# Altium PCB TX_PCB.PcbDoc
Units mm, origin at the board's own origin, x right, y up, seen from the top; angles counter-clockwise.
Board outline 84.96 x 70.99 mm, 2 copper layers (Top Layer, Bottom Layer); 90 components, 66 nets, 345 pads, 0 vias.
Unrouted connection lines stored in the file: 215.
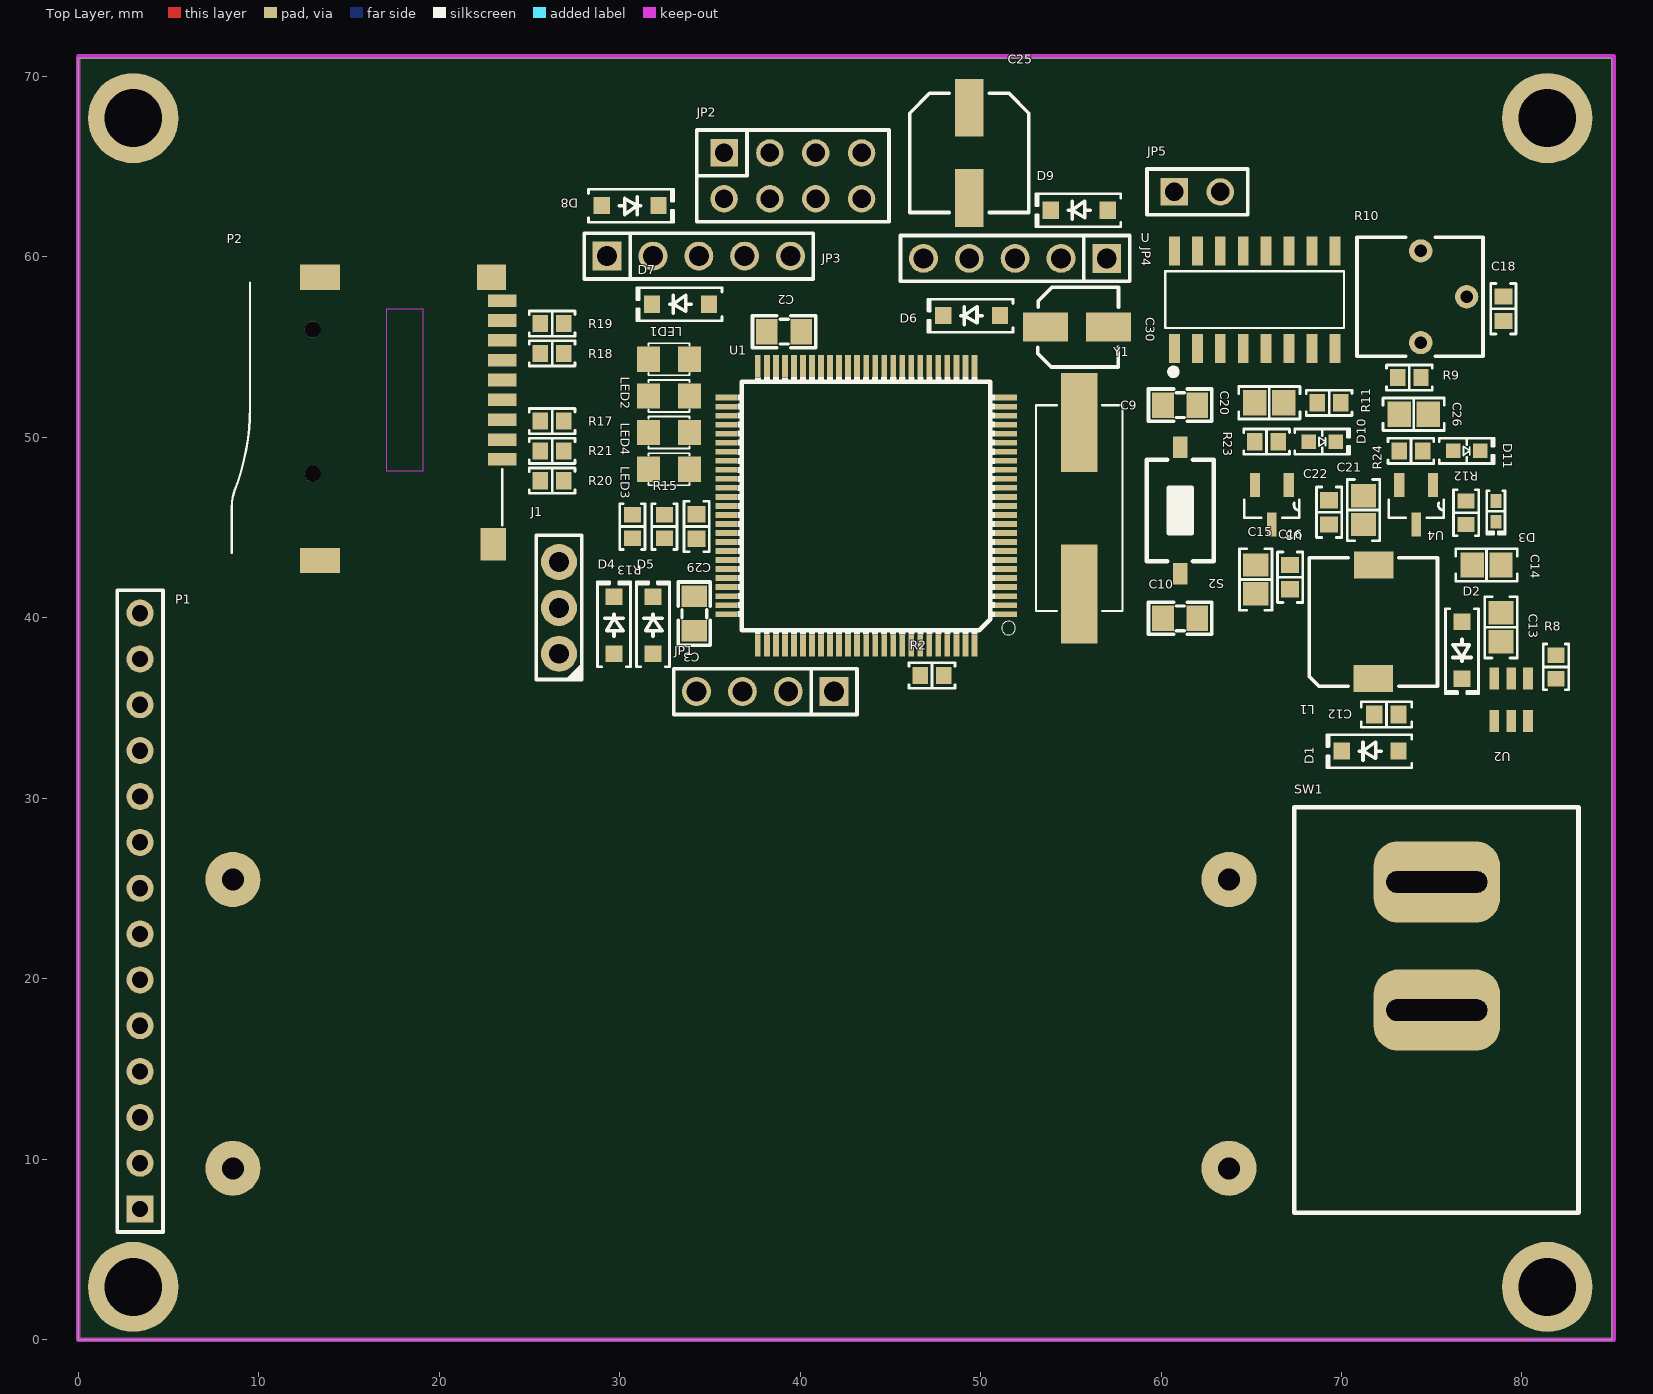
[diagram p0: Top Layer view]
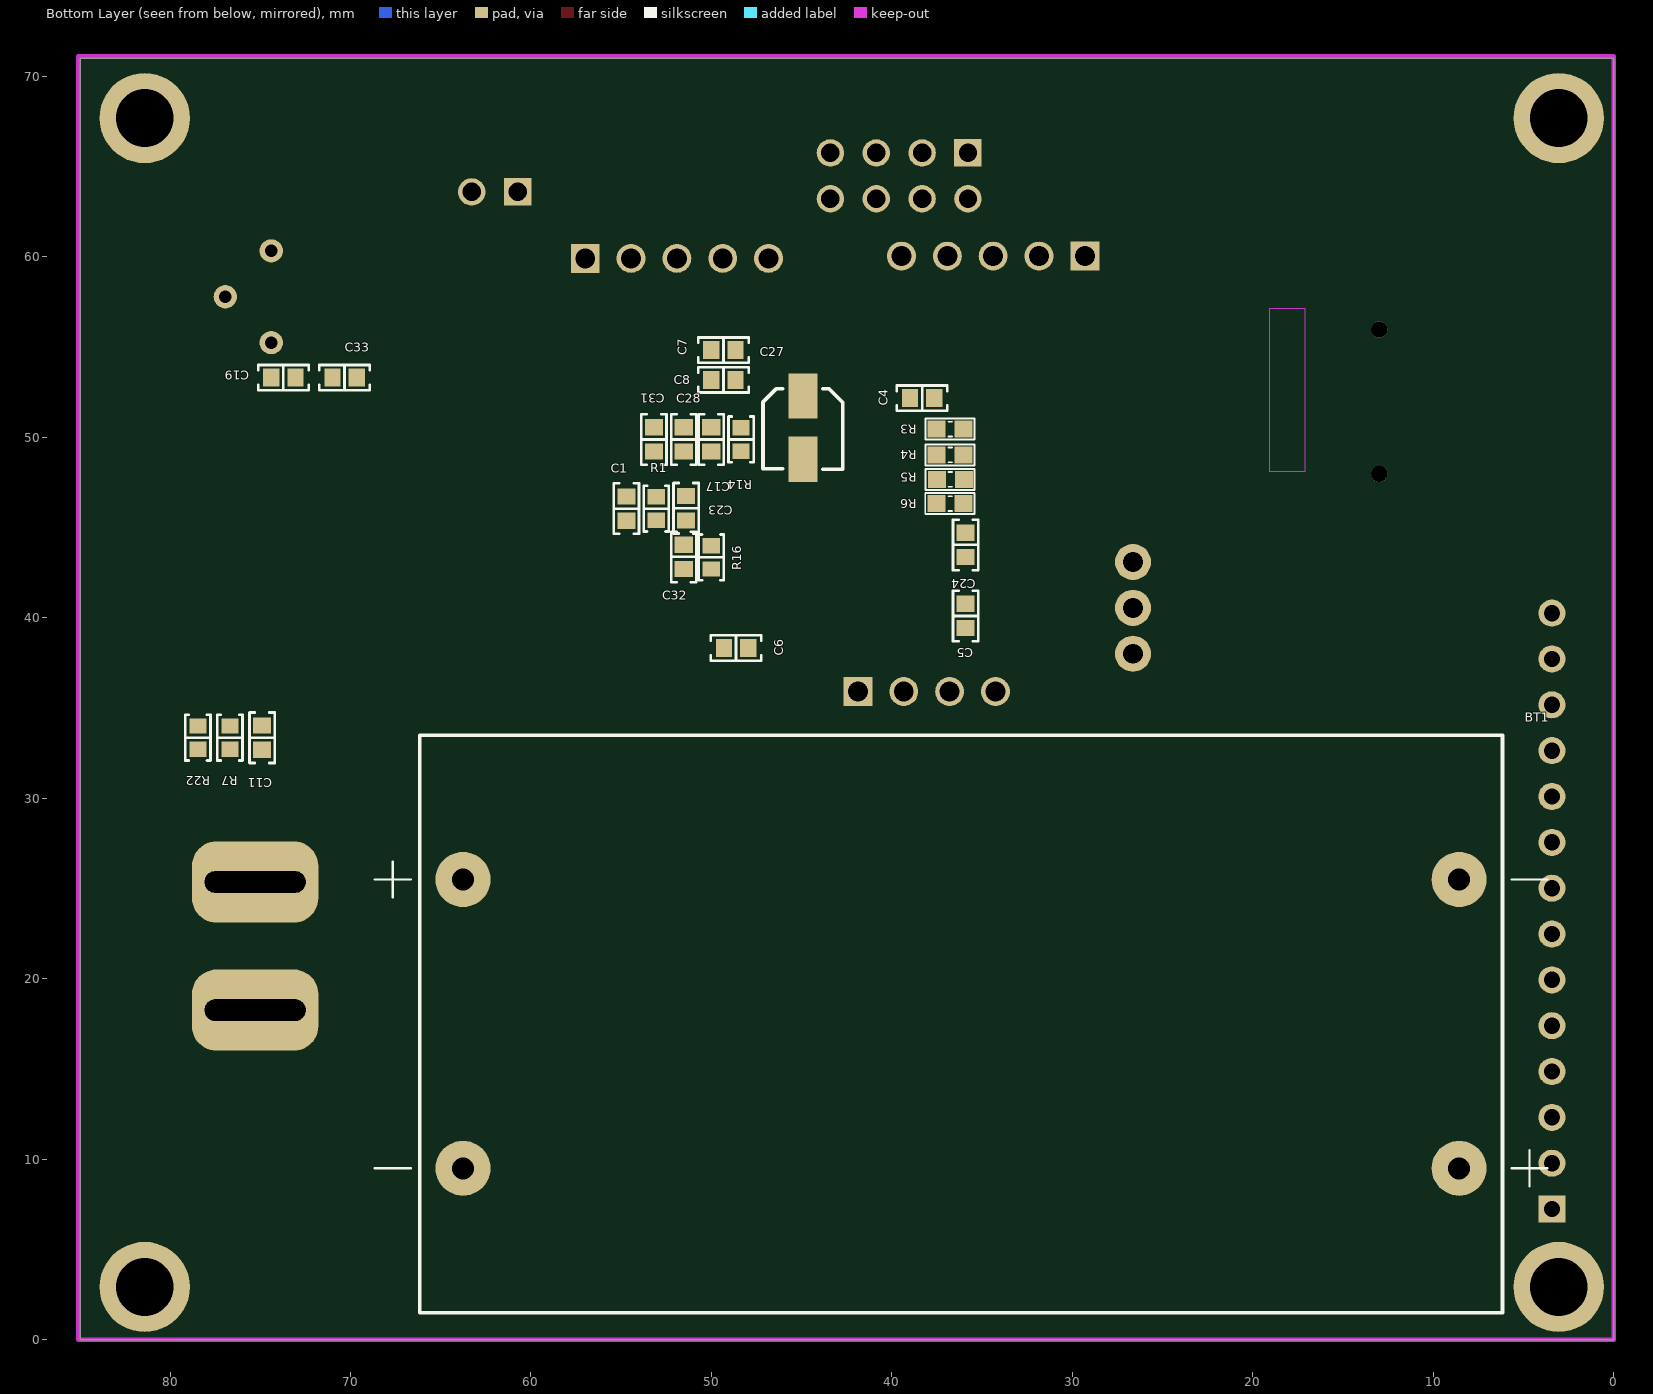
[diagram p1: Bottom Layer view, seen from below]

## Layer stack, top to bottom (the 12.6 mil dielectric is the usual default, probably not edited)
Top Solder: solder mask 0.0102, Solder Resist, Dk 3.5
Top Layer: signal copper 0.0356
Dielectric 1: dielectric 0.32, FR-4, Dk 4.8
Bottom Layer: signal copper 0.0356
Bottom Solder: solder mask 0.0102, Solder Resist, Dk 3.5

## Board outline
0,0 0,70.993 84.963,70.993 84.963,0

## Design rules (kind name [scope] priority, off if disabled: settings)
Clearance [All] p1: gap=0.127 ignorepadtopadclearanceinfootprint=FALSE
PolygonConnect [All] p1: connectstyle=Relief reliefconductorwidth=0.254 reliefentries=4 polygonreliefangle="90 Angle" airgapwidth=0.254
RoutingVias [All] p1: holewidth=0.711 width=1.27 viastyle="Through Hole" minholewidth=0.711 minwidth=1.27 maxholewidth=0.711 maxwidth=1.27
SolderMaskExpansion [All] p1: expansion=0.102 istentingtop=FALSE
Width [All] p1: maxlimit=0.254 minlimit=0.254 preferedwidth=0.254
30 further rules are at their usual default settings.

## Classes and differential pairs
component class Audio: C18 C19 C33 JP5 P2 R9 R10 R11 R17 R18 R19 R20 R21 U
component class Power_2: BT1 C11 C12 C13 C14 C15 C16 C20 C21 C22 C26 D1 D2 D3 D10 D11 L1 R7 R8 R12 R22 R23 R24 SW1 U2 U3 U4
component class MAIN_TX: C1 C2 C3 C4 C5 C6 C7 C8 C9 C10 C17 C23 C24 C25 C27 C28 C29 C30 C31 C32 D4 D5 D6 D7 D8 D9 J1 JP1 JP2 JP3 JP4 LED1 LED2 LED3 LED4 P1 R1 R2 R3 R4 R5 R6 R13 R14 R15 R16 S2 U1 Y1

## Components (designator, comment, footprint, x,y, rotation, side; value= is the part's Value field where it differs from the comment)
BT1 "18650" "DE PIN 18650 X2" 36.168,17.499 r180 bottom
C1 "0.1 µF" "CAP 0603_1608" 54.71,46.051 r90 bottom
C2 "2.2uF" "tu 0805" 39.115,55.853 r180 top
C3 "2.2uF" "tu 0805" 34.136,40.232 r90 top
C4 "0.1 µF" "CAP 0603_1608" 38.327,52.17 r180 bottom
C5 "=Value" "CAP 0603_1608" 35.914,40.105 r270 bottom
C6 "0.1 µF" "CAP 0603_1608" 48.636,38.327 r0 bottom
C7 "=Value" "CAP 0603_1608" 49.336,54.837 r180 bottom
C8 "=Value" "CAP 0603_1608" 49.336,53.186 r180 bottom
C9 "20pF" "tu 0805" 61.06,51.789 r0 top
C10 "20pF" "tu 0805" 61.06,39.978 r0 top
C11 "10000 pF" "CAP 0603_1608" 74.903,33.359 r270 bottom
C12 "10000 pF" "CAP 0603_1608" 72.49,34.644 r0 top
C13 "10 µF" "CAP 0805_2012" 78.84,39.47 r270 top
C14 "22 µF" "CAP 0805_2012" 78.04,42.927 r180 top
C15 "10 µF" "CAP 0805_2012" 65.251,42.127 r90 top
C16 "0.1µF" "CAP 0603_1608" 67.156,42.252 r90 top
C17 "0.1 µF" "CAP 0603_1608" 50.011,49.884 r270 bottom
C18 "0.22 µF" "CAP 0603_1608" 78.967,57.123 r90 top
C19 "0.1 µF" "CAP 0603_1608" 73.72,53.313 r0 bottom
C20 "10 µF" "CAP 0805_2012" 66,51.916 r180 top
C21 "10 µF" "CAP 0805_2012" 71.22,45.97 r270 top
C22 "0.1µF" "CAP 0603_1608" 69.315,45.845 r270 top
C23 "0.1 µF" "CAP 0603_1608" 51.408,46.074 r270 bottom
C24 "0.1 µF" "CAP 0603_1608" 35.914,44.042 r270 bottom
C25 "220 µF" "CAP ALSMD 6.6MM H6.1MM" 49.376,65.759 r270 top
C26 "10 µF" "CAP 0805_2012" 74.001,51.281 r180 top
C27 "1 µF" "CAP ALSMD 4.3MM H5.4MM" 44.931,50.534 r270 bottom
C28 "0.1 µF" "CAP 0603_1608" 51.535,49.884 r270 bottom
C29 "0.1 µF" "CAP 0603_1608" 34.263,45.058 r270 top
C30 "1 µF" "CAP ALSMD 4.3MM H5.4MM" 55.345,56.107 r0 top
C31 "0.1 µF" "CAP 0603_1608" 53.186,49.884 r90 bottom
C32 "1 µF" "CAP 0603_1608" 51.535,43.376 r270 bottom
C33 "1 µF" "CAP 0603_1608" 70.331,53.313 r180 bottom
D1 "1N5819HW-7-F" SOD-123 71.59,32.612 r180 top
D2 "1N5819HW-7-F" SOD-123 76.681,38.202 r270 top
D3 "Green" "LED 0402_1005 GREEN" 78.558,45.897 r270 top
D4 "1N5819HW-7-F" SOD-123 29.691,39.586 r90 top
D5 "1N5819HW-7-F" SOD-123 31.85,39.586 r90 top
D6 "1N5819HW-7-F" SOD-123 49.503,56.742 r180 top
D7 "1N5819HW-7-F" SOD-123 33.374,57.377 r180 top
D8 "1N5819HW-7-F" SOD-123 30.58,62.838 r0 top
D9 "1N5819HW-7-F" SOD-123 55.472,62.584 r180 top
D10 "Yellow" "LED 0603_1608 YELLOW" 68.934,49.757 r0 top
D11 "Yellow" "LED 0603_1608 YELLOW" 76.935,49.249 r0 top
J1 "M20-7820342" "HARWIN M20-7820345" 26.643,40.551 r180 top
JP1 "JP 1x4 2.54" "JP 1x4 DT" 41.883,35.914 r180 top
JP2 "JP 2x4 2.54" "JP 2x4 CT" 39.597,64.489 r0 top
JP3 "JP 1x5 2.54" "JP 1x5 DT" 29.31,60.044 r0 top
JP4 "JP 1x5 2.54" "JP 1x5 DT" 56.996,59.917 r180 top
JP5 "JP 1x2 2.54" "JP 1x2 CT" 60.744,63.6 r0 top
L1 "10µH" "TDK SLF7032" 71.773,39.777 r90 top
LED1 "LED 0805" LED-0805-Red 33.882,54.329 r180 top
LED2 "LED 0805" LED-0805-Yellow 33.882,52.297 r180 top
LED3 "LED 0805" LED-0805-Green 33.882,48.233 r180 top
LED4 "LED 0805" LED-0805-Orange 33.882,50.265 r180 top
P1 "Header 14" HDR1X14 3.429,7.239 r90 top
P2 "ST-TF-003A" SUNTECH_ST-TF-003A 18.165,52.297 r270 top
R1 "100 kOhms" "RES 0603_1608" 53.059,46.051 r270 bottom
R2 "10 kOhms" "RES 0603_1608" 47.311,36.803 r0 top
R3 "680R" "tro smd 0603" 36.774,50.457 r0 bottom
R4 "680R" "tro smd 0603" 36.773,49.022 r0 bottom
R5 "680R" "tro smd 0603" 36.762,47.668 r0 bottom
R6 "680R" "tro smd 0603" 36.778,46.328 r0 bottom
R7 "52.3 kOhms" "RES 0603_1608" 76.681,33.359 r270 bottom
R8 "100 kOhms" "RES 0603_1608" 81.888,37.277 r90 top
R9 "4.7 kOhms" "RES 0603_1608" 73.76,53.313 r0 top
R10 "10 kOhms" "BOURNS TRIMPOT 3362P-1" 74.649,57.791 r270 top
R11 "10 kOhms" "RES 0603_1608" 69.315,51.916 r180 top
R12 "1 kOhms" "RES 0603_1608" 76.904,45.82 r270 top
R13 "10 kOhms" "RES 0603_1608" 30.707,45.058 r270 top
R14 "47 Ohms" "RES 0603_1608" 48.36,49.884 r90 bottom
R15 "20 kOhms" "RES 0603_1608" 32.485,45.058 r270 top
R16 "0 Ohms" "RES 0603_1608" 50.011,43.351 r270 bottom
R17 "4.7 kOhms" "RES 0603_1608" 26.262,50.9 r0 top
R18 "4.7 kOhms" "RES 0603_1608" 26.262,54.648 r0 top
R19 "4.7 kOhms" "RES 0603_1608" 26.262,56.299 r0 top
R20 "4.7 kOhms" "RES 0603_1608" 26.262,47.598 r0 top
R21 "4.7 kOhms" "RES 0603_1608" 26.262,49.249 r0 top
R22 "10 kOhms" "RES 0603_1608" 78.459,33.359 r90 bottom
R23 "680 Ohms" "RES 0603_1608" 65.85,49.757 r180 top
R24 "680 Ohms" "RES 0603_1608" 73.851,49.249 r180 top
S2 "SW-SMD" SW-SMD 61.06,45.947 r90 top
SW1 "ROCKET SWITCH-10A" SW_2ARS_TH 75.259,25.31 r0 top
U "PAM8403DR" SOIC127P605X150-16N 65.189,57.631 r90 top
U1 "MCU-STM32F407VET6(LQFP100)" LQFP100-0.5-13.8X13.8MM 43.661,46.201 r180 top
U2 "LM2734YMK" SOT95P285X100-6N 79.399,35.458 r90 top
U3 "MCP1700T-3302E/TT" SOT95P237X112-3N 66.14,46.262 r270 top
U4 "MCP1700T-3302E/TT" SOT95P237X112-3N 74.141,46.262 r270 top
Y1 "ECS-80-S-5P-TR" XTAL_ECS-80-S-5P-TR 55.472,46.074 r270 top

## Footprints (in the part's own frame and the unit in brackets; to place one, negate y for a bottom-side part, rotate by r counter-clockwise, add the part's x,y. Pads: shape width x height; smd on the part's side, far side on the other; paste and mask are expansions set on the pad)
"BOURNS TRIMPOT 3362P-1" [mm] "3362 -1/4 ? Square Trimpot® Trimming Potentiometer"
  round 1.29 hole 0.69: 1(-2.54,-0.254) 2(0,2.286) 3(2.54,-0.254)
  silkscreen extent -3.3,-3.79 3.3,3.2, body extent -3.3,-3.79 3.3,3.2, height 4.7
"CAP 0603_1608" [mm] "Chip Capacitor, 2-Leads, Body 1.60x0.80mm, IPC Medium Density"
  rect 0.9x1 smd: 1(-0.675,0) 2(0.675,0)
  silkscreen extent -1.4,-0.7 1.4,0.7, body extent -0.8,-0.41 0.8,0.41, height 0.82
"CAP 0805_2012" [mm] "Chip Capacitor, 2-Leads, Body 2.00x1.20mm, IPC Medium Density"
  rect 1.3x1.4 smd: 1(-0.8,0) 2(0.8,0)
  silkscreen extent -1.7,-0.9 1.7,0.9, body extent -1,-0.64 1,0.64, height 1.26
"CAP ALSMD 4.3MM H5.4MM" [mm] "Aluminum Electrolytic Capacitor, Body 4.30x4.30x5.40mm, IPC Low Density"
  rect 2.5x1.6 smd: 1(-1.75,0) 2(1.75,0)
  silkscreen extent -2.17,-2.21 2.3,2.2, body extent -2.3,-2.2 2.3,2.2, height 5.4
"CAP ALSMD 6.6MM H6.1MM" [mm] "Aluminum Electrolytic Capacitor, Body 6.60x6.60x6.10mm, IPC Low Density"
  rect 3.2x1.6 smd: 1(-2.5,0) 2(2.5,0)
  silkscreen extent -3.3,-3.3 3.3,3.3, body extent -3.5,-3.3 3.5,3.3, height 6.1
"DE PIN 18650 X2" [mil] "2-cell AA battery holder"
  round 120 hole 48: 1(-1086.61,314.96) 1(1086.61,314.96) 2(-1086.61,-314.96) 2(1086.61,-314.96)
  silkscreen extent -1280,-630 1280,630, body extent -1181,-630 1181,630, height 657
"HARWIN M20-7820345" [mm] "2.54mm DIL PC TAIL PIN HEADER ASSEMBLY"
  round 2 hole 1.1: 1(0,2.54) 2(0,0) 3(0,-2.54)
  silkscreen extent -1.27,-4.03 1.27,4, body extent -1.25,-4.01 1.25,4.01, height 8.5
HDR1X14 [mm] "Connector; Header; 14 Position"
  rect 1.5x1.5 hole 0.9: 1(0,0)
  round 1.5 hole 0.9: 2(2.54,0) 3(5.08,0) 4(7.62,0) 5(10.16,0) 6(12.7,0) 7(15.24,0) 8(17.78,0) 9(20.32,0) 10(22.86,0) 11(25.4,0) 12(27.94,0) 13(30.48,0) 14(33.02,0)
  silkscreen extent -1.27,-1.27 34.29,1.27, body extent -1.27,-1.27 34.29,1.27, height 7
"JP 1x2 CT" [mm] "JP 1x2 CT"
  rect 1.52x1.52 hole 1.02: 1(0,0)
  round 1.52 hole 1.02: 2(2.54,0)
  silkscreen extent -1.52,-1.27 4.06,1.27, body extent -1.52,-1.25 4.06,1.25, height 8.51
"JP 1x4 DT" [mm] "4 pins, 1 row, straight, gold plating"
  rect 1.6x1.6 hole 1.1: 1(0,0)
  round 1.6 hole 1.1: 2(2.54,0) 3(5.08,0) 4(7.62,0)
  silkscreen extent -1.27,-1.27 8.89,1.27, body extent -1.27,-1.27 8.89,1.27, height 8.54
"JP 1x5 DT" [mm] "5 pins, 1 row, straight, gold plating"
  rect 1.6x1.6 hole 1.1: 1(0,0)
  round 1.6 hole 1.1: 2(2.54,0) 3(5.08,0) 4(7.62,0) 5(10.16,0)
  silkscreen extent -1.27,-1.27 11.43,1.27, body extent -1.27,-1.27 11.43,1.27, height 8.54
"JP 2x4 CT" [mm] "8 pins, dual row, straight, gold plating"
  rect 1.52x1.52 hole 1.02: 1(-3.81,1.27)
  round 1.52 hole 1.02: 2(-1.27,1.27) 3(1.27,1.27) 4(3.81,1.27) 5(3.81,-1.27) 6(1.27,-1.27) 7(-1.27,-1.27) 8(-3.81,-1.27)
  silkscreen extent -5.33,-2.54 5.33,2.54, body extent -5.33,-2.54 5.33,2.54, height 8.51
"LED 0402_1005 GREEN" [mm] "Chip Diode, 2-Leads, Body 1.00x0.50mm, IPC Medium Density"
  rect 0.75x0.6 smd: 1(-0.575,0) 2(0.575,0)
  silkscreen extent -1.14,-0.51 1.27,0.51, body extent -0.5,-0.25 0.5,0.25, height 0.21
"LED 0603_1608 YELLOW" [mm] "Chip Diode, 2-Leads, Body 1.60x0.80mm, IPC Medium Density"
  rect 0.8x0.8 smd: 1(-0.75,0) 2(0.75,0)
  silkscreen extent -1.52,-0.7 1.52,0.7, body extent -0.8,-0.4 0.8,0.4, height 0.53
LED-0805-Green [mil]
  rect 50x55 smd: 1(0,0) 2(90,0)
  silkscreen extent 0,-35 90,35, body extent 5,-25 85,25, height 43
LED-0805-Orange [mil]
  rect 50x55 smd: 1(0,0) 2(90,0)
  silkscreen extent 0,-35 90,35, body extent 5,-25 85,25, height 43
LED-0805-Red [mil]
  rect 50x55 smd: 1(0,0) 2(90,0)
  silkscreen extent 0,-35 90,35, body extent 5,-25 85,25, height 43
LED-0805-Yellow [mil]
  rect 50x55 smd: 1(0,0) 2(90,0)
  silkscreen extent 0,-35 90,35, body extent 5,-25 85,25, height 43
LQFP100-0.5-13.8X13.8MM [mm]
  rect 1.2x0.32 smd: 1(-7.75,6) 2(-7.75,5.5) 3(-7.75,5) 4(-7.75,4.5) 5(-7.75,4) 6(-7.75,3.5) 7(-7.75,3) 8(-7.75,2.5) 9(-7.75,2) 10(-7.75,1.5) 11(-7.75,1) 12(-7.75,0.5) 13(-7.75,0) 14(-7.75,-0.5) 15(-7.75,-1) 16(-7.75,-1.5) 17(-7.75,-2) 18(-7.75,-2.5) 19(-7.75,-3) 20(-7.75,-3.5) 21(-7.75,-4) 22(-7.75,-4.5) 23(-7.75,-5) 24(-7.75,-5.5) 25(-7.75,-6) 51(7.75,-6) 52(7.75,-5.5) 53(7.75,-5) 54(7.75,-4.5) 55(7.75,-4) 56(7.75,-3.5) 57(7.75,-3) 58(7.75,-2.5) 59(7.75,-2) 60(7.75,-1.5) 61(7.75,-1) 62(7.75,-0.5) 63(7.75,0) 64(7.75,0.5) 65(7.75,1) 66(7.75,1.5) 67(7.75,2) 68(7.75,2.5) 69(7.75,3) 70(7.75,3.5) 71(7.75,4) 72(7.75,4.5) 73(7.75,5) 74(7.75,5.5) 75(7.75,6)
  rect 0.32x1.2 smd: 26(-6,-7.75) 27(-5.5,-7.75) 28(-5,-7.75) 29(-4.5,-7.75) 30(-4,-7.75) 31(-3.5,-7.75) 32(-3,-7.75) 33(-2.5,-7.75) 34(-2,-7.75) 35(-1.5,-7.75) 36(-1,-7.75) 37(-0.5,-7.75) 38(0,-7.75) 39(0.5,-7.75) 40(1,-7.75) 41(1.5,-7.75) 42(2,-7.75) 43(2.5,-7.75) 44(3,-7.75) 45(3.5,-7.75) 46(4,-7.75) 47(4.5,-7.75) 48(5,-7.75) 49(5.5,-7.75) 50(6,-7.75) 76(6,7.75) 77(5.5,7.75) 78(5,7.75) 79(4.5,7.75) 80(4,7.75) 81(3.5,7.75) 82(3,7.75) 83(2.5,7.75) 84(2,7.75) 85(1.5,7.75) 86(1,7.75) 87(0.5,7.75) 88(0,7.75) 89(-0.5,7.75) 90(-1,7.75) 91(-1.5,7.75) 92(-2,7.75) 93(-2.5,7.75) 94(-3,7.75) 95(-3.5,7.75) 96(-4,7.75) 97(-4.5,7.75) 98(-5,7.75) 99(-5.5,7.75) 100(-6,7.75)
  silkscreen extent -8.27,-7.13 7.11,7.15, body extent -8,-8 8,8, height 1.6
"RES 0603_1608" [mm] "Chip Resistor, 2-Leads, Body 1.60x0.80mm, IPC Medium Density"
  rect 0.85x0.95 smd: 1(-0.65,0) 2(0.65,0)
  silkscreen extent -1.27,-0.7 1.27,0.7, body extent -0.8,-0.4 0.8,0.4, height 0.45
SOD-123 [mm] "SOD, 2-Leads, Body 1.55x3.70mm, IPC Medium Density"
  rect 0.9x0.95 smd: 1(-1.575,0) 2(1.575,0)
  silkscreen extent -2.3,-0.92 2.41,0.92, body extent -1.86,-0.78 1.86,0.77, height 1.35
SOIC127P605X150-16N [mm]
  rect 1.6x0.6 smd: 1(-2.7,4.445) 2(-2.7,3.175) 3(-2.7,1.905) 4(-2.7,0.635) 5(-2.7,-0.635) 6(-2.7,-1.905) 7(-2.7,-3.175) 8(-2.7,-4.445) 9(2.7,-4.445) 10(2.7,-3.175) 11(2.7,-1.905) 12(2.7,-0.635) 13(2.7,0.635) 14(2.7,1.905) 15(2.7,3.175) 16(2.7,4.445)
  silkscreen extent -4.14,-4.95 1.58,4.95
SOT95P237X112-3N [mil]
  rect 52x22 smd: 1(-43,37) 2(-43,-37)
  rect 52x20 smd: 3(43,0)
  silkscreen extent -11,-60 28,60
SOT95P285X100-6N [mil]
  rect 48x21 smd: 1(-46,37) 2(-46,0) 3(-46,-37) 4(46,-37) 5(46,0) 6(46,37)
SUNTECH_ST-TF-003A [mm]
  rect 0.7x1.6 smd: 1(3.52,5.33) 2(2.42,5.33) 3(1.32,5.33) 4(0.22,5.33) 5(-0.88,5.33) 6(-1.98,5.33) 7(-3.08,5.33) 8(-4.18,5.33) 9(-5.28,5.33)
  rect 1.4x1.6 smd: G1(-6.58,4.73)
  rect 1.4x2.2 smd: G2(-6.58,-4.77) G3(9.12,-4.77)
  rect 1.8x1.4 smd: G4(8.22,4.83)
  round 0.9 hole 0.9 unplated: ""(-3.68,-5.17) ""(4.32,-5.17)
  Keep-Out Layer region: 4.172,-1.073 -4.833,-1.073 -4.833,0.928 4.172,0.928
  silkscreen extent -6.29,-9.66 8.7,5.33
SW-SMD [mm] "Switch SMD type"
  rect 1.2x0.8 smd: 1(-3.5,0) 2(3.5,0)
  silkscreen extent -2.82,-1.85 2.82,1.85, body extent -3.05,-1.85 3.05,1.85, height 2.5
SW_2ARS_TH [mm] "CASE: TH"
  rrect60% 7x4.5 hole 1.2 slot 5.6 at 0 deg mask+0.076: 1(0.025,0.051) 2(0.025,-7.049)
  silkscreen extent -7.87,-18.29 7.87,4.19, body extent -7.47,-17.9 7.53,3.8, height 17.81
"TDK SLF7032" [mm] "Power Inductor, 2-Leads, TDK, SLF7032T-221MR29-2PF"
  rect 1.5x2.2 smd: 1(-3.15,0.013) 2(3.15,-0.012)
  silkscreen extent -3.56,-3.55 3.56,3.55, body extent -3.56,-3.56 3.56,3.54, height 3.39
"tro smd 0603" [mm] "Chip Capacitor, 2-Leads, Body 1,60x0,80mm, IPC Medium Density"
  rect 1x0.95 smd mask+0.076: 1(-0.75,0) 2(0.75,0)
  silkscreen extent -1.35,-0.58 1.37,0.58, body extent -0.82,-0.42 0.82,0.43, height 0.44
"tu 0805" [mm] "Compoment SMD 80x50mil"
  rect 1.2x1.4 smd: 1(-0.946,-0.003) 2(0.954,-0.003)
  silkscreen extent -1.75,-0.89 1.75,0.89, body extent -1.01,-0.64 1.01,0.63, height 0.61
XTAL_ECS-80-S-5P-TR [mm]
  rect 5.5x2 smd: 1(-4.75,0) 2(4.75,0)
  silkscreen extent -5.7,-2.4 5.7,2.4

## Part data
BT1: library part "De Pin 18650 x2", "De Pin 18650 x2"
C1 C4 C6 C17 C23 C28 C31: library part C0603C104M8RAC7867, "CAP CER 0.1UF 10V X7R 0603", Device Package="0603 (1608 Metric)", manufacturer=KEMET, Operating Temperature="-55°C ~ 125°C", Supplier Part Number 1=399-C0603C104M8RAC7867CT-ND, Temperature Coefficient=X7R, Tolerance=±20%, Voltage - Rated=10V
C2 C3: library part "Tu 0805 225 25V 10%", "Dán"
C5 C7 C8: library part C0603C104M8RAC7867, "CAP CER 0.1UF 10V X7R 0603", Capacitance="0.1 µF", Device Package="0603 (1608 Metric)", manufacturer=KEMET, Operating Temperature="-55°C ~ 125°C", Supplier Part Number 1=399-C0603C104M8RAC7867CT-ND, Temperature Coefficient=X7R, Tolerance=±20%, Voltage - Rated=10V
C9 C10: library part "Tu 0805 20pF 50V 10%", "Dán"
C11 C12: library part C0603C103K4RECAUTO, "CAP CER 0603 10NF 16V X7R 10%", Device Package="0603 (1608 Metric)", manufacturer=KEMET, Operating Temperature="-55°C ~ 125°C", Ratings=AEC-Q200, Supplier Part Number 1=399-17880-1-ND, Temperature Coefficient=X7R, Tolerance=±10%, Voltage - Rated=16V
C13: library part CL21X106KAYNNNE, "CAP CER 10UF 25V X6S 0805", Device Package="0805 (2012 Metric)", manufacturer="Samsung Electro-Mechanics", Operating Temperature="-55°C ~ 105°C", Supplier Part Number 1=1276-6698-1-ND, Temperature Coefficient=X6S, Tolerance=±10%, Voltage - Rated=25V
C14: library part CL21A226KQQNNNE, "CAP CER 22UF 6.3V X5R 0805", Device Package="0805 (2012 Metric)", manufacturer="Samsung Electro-Mechanics", Operating Temperature="-55°C ~ 85°C", Supplier Part Number 1=1276-2907-1-ND, Temperature Coefficient=X5R, Tolerance=±10%, Voltage - Rated=6.3V
C15 C20 C21 C26: library part C2012X6S1C106K125AC, "CAP CER 10UF 16V X6S 0805", Device Package="0805 (2012 Metric)", manufacturer="TDK Corporation", Operating Temperature="-55°C ~ 105°C", Supplier Part Number 1=445-7611-1-ND, Temperature Coefficient=X6S, Tolerance=±10%, Voltage - Rated=16V
C16 C22: library part 0603YC104K4T4A, "CAP CER 0.1UF 16V X7R 0603", Device Package="0603 (1608 Metric)", manufacturer="AVX Corporation", Operating Temperature="-55°C ~ 125°C", Ratings=AEC-Q200, Supplier Part Number 1=478-9382-1-ND, Temperature Coefficient=X7R, Tolerance=±10%, Voltage - Rated=16V
C18: library part KAM15AR71A224KT, "CAP CER 0.22UF 10V X7R 0603", Device Package="0603 (1608 Metric)", manufacturer="KYOCERA AVX", Operating Temperature="-55°C ~ 125°C", Ratings=AEC-Q200, Supplier Part Number 1=478-KAM15AR71A224KTCT-ND, Temperature Coefficient=X7R, Tolerance=±10%, Voltage - Rated=10V
C19: library part CL10F104ZB8NNNC, "CAP CER 0.1UF 50V Y5V 0603", Device Package="0603 (1608 Metric)", manufacturer="Samsung Electro-Mechanics", Operating Temperature="-30°C ~ 85°C", Supplier Part Number 1=1276-1012-1-ND, Temperature Coefficient="Y5V (F)", Tolerance="-20%, +80%", Voltage - Rated=50V
C24 C29: library part VJ0603Y104KXQCW1BC, "CAP CER 0.1UF 10V X7R 0603", Device Package="0603 (1608 Metric)", manufacturer="Vishay Vitramon", Operating Temperature="-55°C ~ 125°C", Supplier Part Number 1=720-1689-1-ND, Temperature Coefficient=X7R, Tolerance=±10%, Voltage - Rated=10V
C25: library part UCM1A221MCL1GS, "CAP ALUM 220UF 20% 10V SMD", Device Package="Radial, Can - SMD", Lifetime @ Temp.="2000 Hrs @ 105°C", manufacturer=Nichicon, Operating Temperature="-55°C ~ 105°C", Ratings=AEC-Q200, Ripple Current @ High Frequency="300 mA @ 100 kHz", Ripple Current @ Low Frequency="150 mA @ 120 Hz", Supplier Part Number 1=493-17470-1-ND, Tolerance=±20%, Voltage - Rated="10 V"
C27 C30: library part EEE-HD1H1R0R, "CAP ALUM 1UF 20% 50V SMD", Device Package="Radial, Can - SMD", Lifetime @ Temp.="5000 Hrs @ 105°C", manufacturer="Panasonic Electronic Components", Operating Temperature="-40°C ~ 105°C", Ratings=AEC-Q200, Ripple Current @ High Frequency="11.9 mA @ 10 kHz", Ripple Current @ Low Frequency="7 mA @ 120 Hz", Supplier Part Number 1=PCE4972CT-ND, Tolerance=±20%, Voltage - Rated="50 V"
C32: library part C0603X105J8RAC7411, "CAP CER 0603 1UF 10V X7R 5%", Device Package="0603 (1608 Metric)", manufacturer=KEMET, Operating Temperature="-55°C ~ 125°C", Supplier Part Number 1=399-C0603X105J8RAC7411CT-ND, Temperature Coefficient=X7R, Tolerance=±5%, Voltage - Rated=10V
C33: library part UMK107ABJ105KAHT, "CAP CER 1UF 50V X5R 0603", Device Package="0603 (1608 Metric)", manufacturer="Taiyo Yuden", Operating Temperature="-55°C ~ 85°C", Ratings=AEC-Q200, Supplier Part Number 1=587-3501-1-ND, Temperature Coefficient=X5R, Tolerance=±10%, Voltage - Rated=50V
D1 D2 D4 D5 D6 D7 D8 D9: "DIODE SCHOTTKY 40V 1A SOD123", Capacitance @ Vr, F="60pF @ 4V, 1MHz", Current - Average Rectified (Io)=1A, Current - Reverse Leakage @ Vr="1 mA @ 40 V", manufacturer="Diodes Incorporated", Operating Temperature - Junction="-65°C ~ 125°C", Package / Case=SOD-123, Supplier Part Number 1=1N5819HW-FDICT-ND, Voltage - DC Reverse (Vr) (Max)="40 V", Voltage - Forward (Vf) (Max) @ If="450 mV @ 1 A"
D3: library part QBLP595-AG15-2897, "LED GREEN CLEAR 0402 SMD", Current - Test=5mA, Device Package="0402 (1005 Metric)", Lens Color=Colorless, manufacturer="QT Brightek (QTB)", Millicandela Rating=16.5mcd, Supplier Device Package=0402, Supplier Part Number 1=1516-QBLP595-AG15-2897CT-ND, Voltage - Forward (Vf) (Typ)=1.9V
D10 D11: library part IN-S63AT5Y, "LED YELLOW CLEAR 0603 SMD", Current - Test=5mA, Device Package="0603 (1608 Metric)", Lens Color=Clear, manufacturer=Inolux, Millicandela Rating=35mcd, Supplier Device Package=0603, Supplier Part Number 1=1830-1066-1-ND, Voltage - Forward (Vf) (Typ)=2V
J1: "CONN RCPT 3POS 0.1 GOLD PCB", Current Rating (Amps)=3A, Insulation Color=Black, manufacturer="Harwin Inc.", Material Flammability Rating="UL94 V-0", Operating Temperature="-40°C ~ 105°C", Supplier Part Number 1=952-1783-ND
JP1: library part "JP 1x4 2.54 Duc Thang", "Cắm"
JP2: library part "JP 2x4 2.54 Cai Thang", "Cắm"
JP3 JP4: library part "JP 1x5 2.54 Duc Thang", "Cắm"
JP5: library part "JP 1x2 2.54 Cai Thang", "Cắm"
L1: library part SLF7032T-100M1R4-2PF, "FIXED IND 10UH 1.4A 63.6 MOHM", Current Rating (Amps)=1.4A, DC Resistance (DCR)="63.6mOhm Max", Device Package=Nonstandard, Inductance Frequency - Test=100kHz, manufacturer="TDK Corporation", Operating Temperature="-40°C ~ 105°C", Supplier Part Number 1=445-1998-1-ND, Tolerance=±20%
LED1: library part "LED 0805 Do", "Dán"
LED2: library part "LED 0805 Vang", "Dán"
LED3: library part "LED 0805 Xanh La", "Dán"
LED4: library part "LED 0805 Cam", "Dán"
P1: "Header, 14-Pin"
P2: "Micro SD Card Socket", Package=None
R1: library part RN73H1JTTD1003B50, "RES 100K OHM 0.1% 1/10W 0603", Device Package="0603 (1608 Metric)", manufacturer="KOA Speer Electronics, Inc.", Operating Temperature="-55°C ~ 155°C", Power (Watts)="0.1W, 1/10W", Ratings=AEC-Q200, Supplier Device Package=0603, Supplier Part Number 1=2019-RN73H1JTTD1003B50CT-ND, Temperature Coefficient=±50ppm/°C, Tolerance=±0.1%
R2 R13: library part CHP0603AFX-1002ELF, "RESHIGHPOWERA 0603 10K 1% 1/3W T", Device Package="0603 (1608 Metric)", manufacturer="Bourns Inc.", Operating Temperature="-55°C ~ 155°C", Power (Watts)="0.333W, 1/3W", Ratings=AEC-Q200, Supplier Device Package=0603, Supplier Part Number 1=118-CHP0603AFX-1002ELFCT-ND, Temperature Coefficient=±100ppm/°C, Tolerance=±1%
R3 R4 R5 R6: library part "Tro 0603 1% 680R", "Dán"
R7: library part ERA-3AEB5232V, "RES SMD 52.3KOHM 0.1% 1/10W 0603", Device Package="0603 (1608 Metric)", manufacturer="Panasonic Electronic Components", Operating Temperature="-55°C ~ 155°C", Power (Watts)="0.1W, 1/10W", Ratings=AEC-Q200, Supplier Device Package=0603, Supplier Part Number 1=P52.3KDBCT-ND, Temperature Coefficient=±25ppm/°C, Tolerance=±0.1%
R8: library part RCA0603100KJNEA, "RES SMD 100K OHM 5% 1/10W 0603", Device Package="0603 (1608 Metric)", manufacturer="Vishay Dale", Operating Temperature="-55°C ~ 155°C", Power (Watts)="0.1W, 1/10W", Ratings=AEC-Q200, Supplier Device Package=0603, Supplier Part Number 1=541-2215-1-ND, Temperature Coefficient=±200ppm/°C, Tolerance=±5%
R9 R17 R18 R19 R20 R21: library part RK73H1JTTD4701D, "RES 4.7K OHM 0.5% 1/10W 0603", Device Package="0603 (1608 Metric)", manufacturer="KOA Speer Electronics, Inc.", Operating Temperature="-55°C ~ 155°C", Power (Watts)="0.1W, 1/10W", Ratings=AEC-Q200, Supplier Device Package=0603, Supplier Part Number 1=2019-RK73H1JTTD4701DCT-ND, Temperature Coefficient=±100ppm/°C, Tolerance=±0.5%
R10: library part 3362P-1-103LF, "TRIMMER 10K OHM 0.5W PC PIN TOP", manufacturer="Bourns Inc.", Power (Watts)="0.5W, 1/2W", Resistive Material=Cermet, Supplier Part Number 1=3362P-103LF-ND, Temperature Coefficient=±100ppm/°C, Tolerance=±10%
R11: library part RT0603DRE0710KL, "RES SMD 10K OHM 0.5% 1/10W 0603", Device Package="0603 (1608 Metric)", manufacturer=Yageo, Operating Temperature="-55°C ~ 155°C", Power (Watts)="0.1W, 1/10W", Supplier Device Package=0603, Supplier Part Number 1=YAG2318CT-ND, Temperature Coefficient=±50ppm/°C, Tolerance=±0.5%
R12: library part RN73R1JTTD1001B25, "RES 1K OHM 0.1% 1/10W 0603", Device Package="0603 (1608 Metric)", manufacturer="KOA Speer Electronics, Inc.", Operating Temperature="-55°C ~ 155°C", Power (Watts)="0.1W, 1/10W", Ratings=AEC-Q200, Supplier Device Package=0603, Supplier Part Number 1=2019-RN73R1JTTD1001B25CT-ND, Temperature Coefficient=±25ppm/°C, Tolerance=±0.1%
R14: library part CRT0603-FY-47R0ELF, "RES SMD 47 OHM 1% 1/10W 0603", Device Package="0603 (1608 Metric)", manufacturer="Bourns Inc.", Operating Temperature="-55°C ~ 155°C", Power (Watts)="0.1W, 1/10W", Supplier Device Package=0603, Supplier Part Number 1=118-CRT0603-FY-47R0ELFCT-ND, Temperature Coefficient=±25ppm/°C, Tolerance=±1%
R15: library part RG1608P-203-B-T5, "RES SMD 20K OHM 0.1% 1/10W 0603", Device Package="0603 (1608 Metric)", manufacturer=Susumu, Operating Temperature="-55°C ~ 155°C", Power (Watts)="0.1W, 1/10W", Ratings=AEC-Q200, Supplier Device Package=0603, Supplier Part Number 1=RG16P20.0KBCT-ND, Temperature Coefficient=±25ppm/°C, Tolerance=±0.1%
R16: library part CR0603AJ/-000ELF, "RES 0 OHM JUMPER 1/10W 0603", Device Package="0603 (1608 Metric)", manufacturer="Bourns Inc.", Operating Temperature="-55°C ~ 155°C", Power (Watts)="0.1W, 1/10W", Ratings=AEC-Q200, Supplier Device Package=0603, Supplier Part Number 1=118-CR0603AJ/-000ELFCT-ND, Tolerance=Jumper
R22: library part TNPU060310K0BZEN00, "RES SMD 10K OHM 0.1% 1/10W 0603", Device Package="0603 (1608 Metric)", manufacturer="Vishay Dale", Operating Temperature="-55°C ~ 125°C", Power (Watts)="0.1W, 1/10W", Ratings=AEC-Q200, Supplier Device Package=0603, Supplier Part Number 1=TNPU10.0KBACT-ND, Temperature Coefficient=±5ppm/°C, Tolerance=±0.1%
R23 R24: library part RT0603CRD07680RL, "RES SMD 680 OHM 0.25% 1/10W 0603", Device Package="0603 (1608 Metric)", manufacturer=Yageo, Operating Temperature="-55°C ~ 155°C", Power (Watts)="0.1W, 1/10W", Supplier Device Package=0603, Supplier Part Number 1=YAG4792CT-ND, Temperature Coefficient=±25ppm/°C, Tolerance=±0.25%
S2: "Switch"
SW1: library part SW1_10A-SRB23A2BBBNN-TH, "Rocker Switch SPDT 10A (AC) 125V Panel Mount, Snap-In", Alternate Part Number-1=NA, Case/Package=TH, manufacturer="ITT C&K", Manufacturer Part Number=SRB23A2BBBNN
U: "Amplifier IC 2-Channel _Stereo_ Class D 16-SOP", Package="SOP-16 Diodes Inc."
U1: "ARMÂ® CortexÂ®-M4 STM32F4 Microcontroller IC 32-Bit Single-Core 168MHz 512KB (512K x 8) FLASH 100-LQFP (14x14)", Package="LQFP-100 STMicroelectronics"
U2: "Buck Switching Regulator IC Positive Adjustable 0.8V 1 Output 1A SOT-23-6 Thin, TSOT-23-6", Package="SOT-23 Texas Instruments"
U3 U4: "Linear Voltage Regulator IC 1 Output 250mA SOT-23-3", Package="SOT-23-3 Microchip"
Y1: "CRYSTAL SMD", Package=None

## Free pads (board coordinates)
  round 5 hole 3.2: 8(3.048,2.921) 8(3.048,67.691) 8(81.407,2.921) 8(81.407,67.691)

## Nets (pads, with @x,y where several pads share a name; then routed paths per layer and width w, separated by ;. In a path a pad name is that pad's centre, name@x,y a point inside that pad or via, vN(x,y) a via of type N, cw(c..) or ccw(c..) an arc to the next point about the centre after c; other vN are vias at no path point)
+5: C11.2 C14.2 C15.2 C16.2 C21.2 C22.2 D1.1 D6.1 D6.2 D7.1 D7.2 D8.2 D9.2 JP3.2 JP4.2 L1.2 P1.14 R7.2 R12.2 U3.3 U4.3 U.4 U.5 U.6 U.12 U.13
+8.4: C13.2 R8.2 R13.1 SW1.2 U2.5
ADC_Pin: C29.2 R13.2 R15.2 U1.67
ADC_VR_ESC: C24.2 J1.2 U1.68
Audio_PWM: R9.1 U1.92
BOOT0: R2.1 U1.94
CLK_SD: P2.5 U1.78
CS_SD: P2.2 R21.1 U1.81
DISPL_CS: P1.12 U1.35
DISPL_DC: P1.10 U1.37
DISPL_LED: P1.7 U1.64
DISPL_MOSI: P1.3 P1.9 U1.32
DISPL_RST: P1.11 U1.34
DISPL_SCK: P1.5 P1.8 U1.30
GND: BT1.2 C1.1 C2.1 C3.1 C4.1 C5.1 C6.1 C7.1 C8.1 C9.2 C10.2 C13.1 C14.1 C15.1 C16.1 C17.1 C19.1 C20.1 C21.1 C22.1 C23.1 C24.1 C25.2 C26.1 C27.2 C28.1 C29.1 C30.2 C31.2 C32.1 C33.1 D2.1 D3.2 D4.1 D8.1 D9.1 D10.2 D11.2 J1.1 JP1.2 JP2.5 JP3.1 JP4.1 LED1.2 LED2.2 LED3.2 LED4.2 P1.13 P2.6 P2.G1 P2.G2 P2.G3 P2.G4 R2.2 R10.1 R15.1 R22.1 S2.1 U1.10 U1.20 U1.27 U1.74 U1.99 U2.2 U3.1 U4.1 U.2 U.11 U.15
JOY1_X: JP3.3 U1.24
JOY1_Y: JP3.4 U1.25
JOY2_X: JP4.3 U1.26
JOY2_Y: JP4.4 U1.29
LED1: R3.1 U1.59
LED2: R4.1 U1.60
LED3: R5.1 U1.61
LED4: R6.1 U1.62
MISO_SD: P2.7 R18.1 U1.79
MOSI_SD: P2.3 R17.1 U1.80
NetBT1_1: BT1.1 SW1.1
NetC11_1: C11.1 R7.1 R22.2 U2.3
NetC12_1: C12.1 D2.2 L1.1 U2.6
NetC12_2: C12.2 D1.2 U2.1
NetC18_1: C18.1 R11.1
NetC18_2: C18.2 R10.2
NetC19_2: C19.2 R9.2 R10.3
NetC33_2: C33.2 U.8
NetD3_1: D3.1 R12.1
NetD10_1: D10.1 R23.1
NetD11_1: D11.1 R24.1
NetJP5_1: JP5.1 U.1
NetJP5_2: JP5.2 U.3
NetLED1_1: LED1.1 R3.2
NetLED2_1: LED2.1 R4.2
NetLED3_1: LED3.1 R5.2
NetLED4_1: LED4.1 R6.2
NetP2_1: P2.1 R20.1
NetP2_8: P2.8 R19.1
NetR8_1: R8.1 U2.4
NetR11_2: R11.2 U.7
NRST: C1.2 R1.1 S2.2 U1.14
OSC_IN: C10.1 U1.12 Y1.2
OSC_OUT: C9.1 U1.13 Y1.1
RF_CE: JP2.6 U1.52
RF_CSN: JP2.3 U1.51
RF_MISO: JP2.8 U1.53
RF_MOSI: JP2.2 U1.54
RF_SCK: JP2.7 U1.47
SWCLK: JP1.3 U1.76
SWDIO: JP1.1 U1.72
TOUCH_CS: P1.4 U1.36
TOUCH_INT: P1.1 U1.33
TOUCH_MISO: P1.2 U1.31
VBAT: C32.2 R16.2 U1.6
VCAP_1: C2.2 U1.49
VCAP_2: C3.2 U1.73
VCCNRF: C25.1 C26.2 JP2.4 R24.2 U4.2
VDD1: C4.2 C5.2 C6.2 C7.2 C8.2 C17.2 C20.2 C23.2 D4.2 D5.1 D5.2 J1.3 JP1.4 P2.4 R1.2 R14.1 R16.1 R17.2 R18.2 R19.2 R20.2 R21.2 R23.2 U1.11 U1.19 U1.28 U1.50 U1.75 U1.100 U3.2
VDDA: C30.1 C31.1 U1.22
VREF+: C27.1 C28.2 R14.2 U1.21
pads on no net: JP2.1 JP3.5 JP4.5 P1.6 P2. P2.9 U1.1 U1.2 U1.3 U1.4 U1.5 U1.7 U1.8 U1.9 U1.15 U1.16 U1.17 U1.18 U1.23 U1.38 U1.39 U1.40 U1.41 U1.42 U1.43 U1.44 U1.45 U1.46 U1.48 U1.55 U1.56 U1.57 U1.58 U1.63 U1.65 U1.66 U1.69 U1.70 U1.71 U1.77 U1.82 U1.83 U1.84 U1.85 U1.86 U1.87 U1.88 U1.89 U1.90 U1.91 U1.93 U1.95 U1.96 U1.97 U1.98 U.9 U.10 U.14 U.16

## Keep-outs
Keep-Out Layer:
  lines w0.254: 0,0 0,71.12 85.09,71.12 85.09,0 0,0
